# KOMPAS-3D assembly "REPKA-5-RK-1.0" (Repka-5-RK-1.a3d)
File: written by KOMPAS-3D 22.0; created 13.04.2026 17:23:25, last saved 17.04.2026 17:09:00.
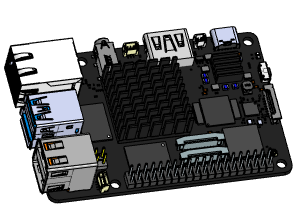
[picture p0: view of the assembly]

Document properties: Автор: Andrey; Полное имя файла: C:\Users\User1\Documents\Работа\Корпуса\Корпус Repka Pi 5\Конструкторская документация\3д модель\Repka_5_3D\Repka-5-RK-1.a3d

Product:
- Component [detail]: BOARD_OUTLINE  | qty 1  | Масса: 0.064273; Комментарий: BOARD_OUTLINE; source file: BOARD_OUTLINE.m3d
- Component [assembly]: COMPONENTS  | qty 1  | Масса: 0.10509; Комментарий: COMPONENTS; source file: COMPONENTS.a3d
- Component [detail]: Радиатор 9x9  | qty 1  | Масса: 0.001885; source file: Радиатор 9х9.m3d
- Component [detail]: Радиатор 25x25  | qty 1  | Масса: 0.020327; source file: Радиатор 25х25.m3d
- Part/product: REPKA-5-RK-1.0
    Масса: 0.191575
    Комментарий: REPKA-5-RK-1.0

Referenced files in C:\Users\User1\Documents\Работа\Корпуса\Корпус Repka Pi 5\Конструкторская документация\3д модель\Repka_5_3D\: BOARD_OUTLINE.m3d, COMPONENTS.a3d, Радиатор 9х9.m3d, Радиатор 25х25.m3d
